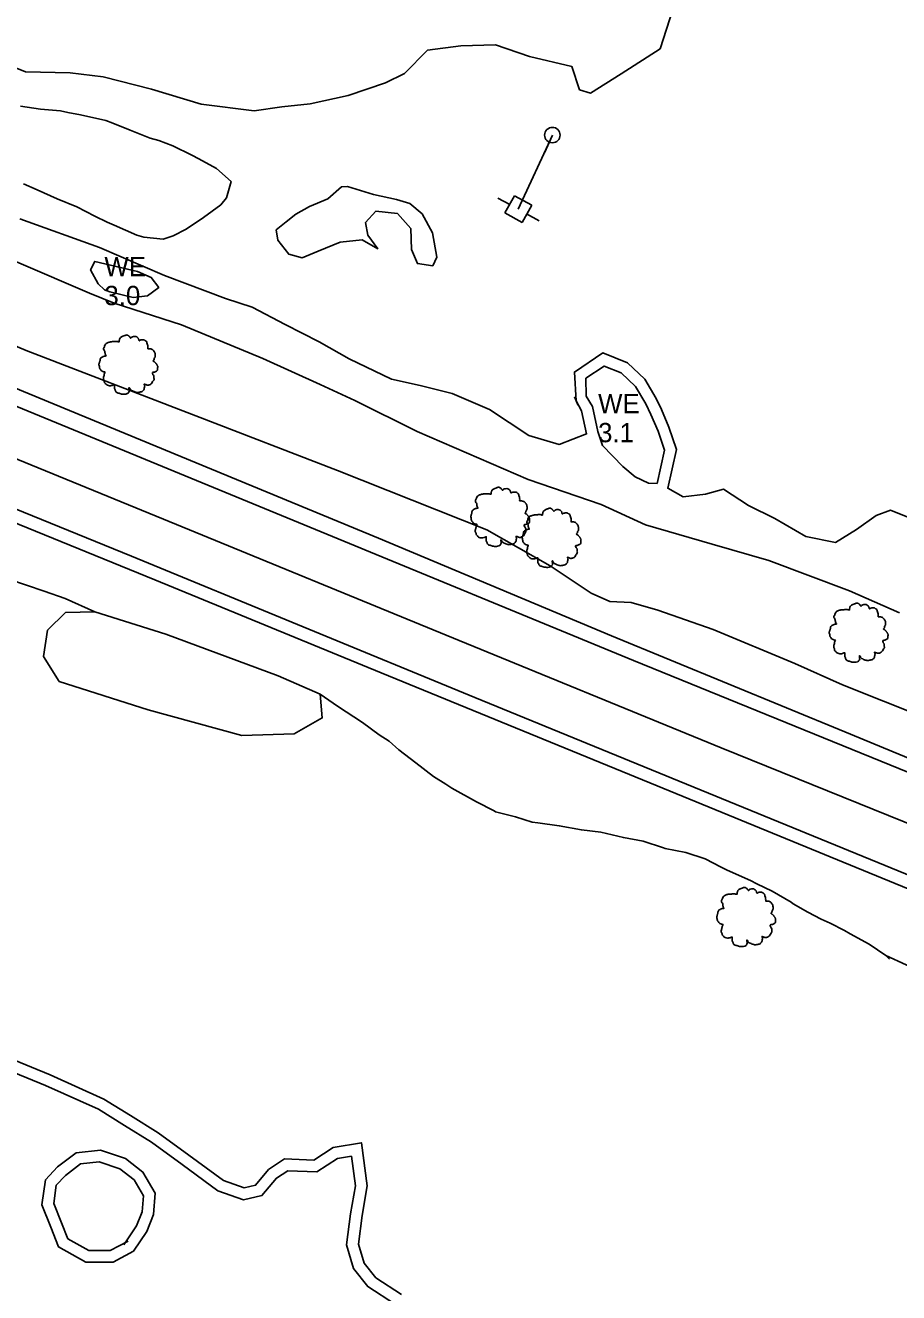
# Model space of a CAD drawing. Extents: x 2160437 to 2172832, y 205694 to 212444.
# Drawn here: x 2165786.1 to 2166012.2, y 209227.2 to 209555.1 of the extents above; entities that cross this region are included whole.
import ezdxf

# ---------------------------------------------------------------- set-up
doc = ezdxf.new("R2010")
doc.units = 0
for name, color, linetype in [('RD_EX_H2O', 7, 'Continuous'), ('RD_EX_H2O_Pond', 7, 'Continuous'), ('RD_EX_H2O_txCode', 7, 'Continuous'), ('RD_EX_LaneStripe', 7, 'Continuous'), ('RD_EX_Road', 7, 'Continuous'), ('RD_EX_UT', 7, 'Continuous'), ('RD_EX_UT_Guy', 7, 'Continuous'), ('RD_EX_VEG', 7, 'Continuous'), ('RD_EX_VEG_ShrubLine', 7, 'Continuous'), ('RD_EX_VEG_TreeLine', 7, 'Continuous')]:
    doc.layers.add(name, color=color, linetype=linetype)

# ---------------------------------------------------------------- blocks, each defined once
blk = doc.blocks.new('T2')
at = {"layer": 'RD_EX_VEG'}
for points in [[(0.05, 7.21), (-0.25, 7.24), (-0.57, 7.14), (-0.82, 7.04), (-1.05, 6.96), (-1.27, 6.86), (-1.57, 6.69), (-1.8, 6.49), (-1.92, 6.24), (-1.97, 6.01), (-2.02, 5.74), (-2.02, 5.56), (-2.15, 5.54), (-2.3, 5.56), (-2.55, 5.64), (-2.8, 5.64), (-3.05, 5.64), (-3.4, 5.61), (-3.75, 5.61), (-4.02, 5.56), (-4.35, 5.51), (-4.72, 5.39), (-5.07, 5.26), (-5.37, 5.01), (-5.62, 4.54), (-5.75, 4.19), (-5.9, 3.94), (-5.75, 3.49), (-5.57, 3.14), (-5.55, 2.94), (-5.47, 2.52), (-5.37, 2.29), (-5.25, 2.09), (-5.32, 2.07), (-5.7, 2.02), (-6, 1.92), (-6.42, 1.69), (-6.64, 1.47), (-6.74, 1.14), (-6.77, 0.79), (-6.87, 0.59), (-6.94, 0.32), (-6.97, 0.24), (-7.02, -0.08), (-6.92, -0.53), (-6.89, -0.88), (-6.77, -1.11), (-6.62, -1.28), (-6.44, -1.53), (-6.05, -1.76), (-5.72, -1.86), (-5.52, -1.88), (-5.7, -2.38), (-5.75, -2.73), (-5.87, -3.13), (-5.87, -3.21), (-5.92, -3.68), (-5.77, -4.01), (-5.7, -4.38), (-5.52, -4.61), (-5.25, -4.91), (-4.92, -5.13), (-4.42, -5.26), (-4.02, -5.23), (-3.45, -5.06), (-3.2, -4.98), (-3.22, -5.16), (-3.2, -5.53), (-3.2, -5.96), (-3.05, -6.28), (-2.95, -6.56), (-2.8, -6.81), (-2.47, -7.03), (-2.07, -7.11), (-1.65, -7.26), (-1.2, -7.33), (-0.7, -7.36), (-0.1, -7.21), (0.18, -7.08), (0.28, -6.91), (0.48, -6.53), (0.43, -6.31), (0.45, -5.71), (0.55, -5.88), (0.73, -6.23), (1.23, -6.53), (1.63, -6.71), (2.1, -6.86), (2.4, -6.93), (2.88, -6.86), (3.25, -6.78), (3.63, -6.66), (3.93, -6.38), (4.1, -6.11), (4.15, -5.83), (4.23, -5.46), (4.28, -5.28)], [(4.28, -5.28), (4.2, -5.11), (4.15, -4.86), (4.23, -4.88), (4.4, -4.93), (4.68, -5.06), (4.9, -5.13), (5.23, -5.11), (5.5, -5.01), (5.95, -4.73), (6.22, -4.26), (6.5, -3.86), (6.57, -3.53), (6.52, -3.31), (6.5, -2.81), (6.3, -2.56), (6.25, -2.43), (6.15, -2.03), (6.22, -1.98), (6.5, -1.93), (6.87, -1.81), (7.15, -1.68), (7.37, -1.51), (7.45, -1.28), (7.42, -0.88), (7.47, -0.48), (7.4, -0.33), (7.3, -0.18), (7.22, 0.02), (7.07, 0.17), (6.97, 0.32), (6.87, 0.42), (6.75, 0.57), (6.57, 0.69), (6.42, 0.74), (6.37, 0.89), (6.52, 1.09), (6.57, 1.19), (6.6, 1.42), (6.82, 1.77), (6.87, 2.17), (6.82, 2.59), (6.77, 2.87), (6.62, 3.14), (6.42, 3.39), (6.3, 3.56), (6.12, 3.69), (5.8, 3.81), (5.55, 3.86), (5.2, 3.86), (5, 3.91), (5.03, 3.96), (5.03, 4.11), (5.03, 4.39), (4.95, 4.84), (4.8, 5.34), (4.8, 5.36), (4.7, 5.61), (4.48, 5.81), (4.3, 5.91), (4.1, 6.04), (3.85, 6.06), (3.55, 6.06), (3.28, 6.01), (3.08, 5.91), (2.9, 5.79), (2.83, 5.94), (2.73, 6.24), (2.68, 6.39), (2.53, 6.56), (2.3, 6.76), (1.85, 6.89), (1.23, 6.81), (0.93, 6.61), (0.78, 6.44), (0.73, 6.56), (0.53, 6.76), (0.43, 6.94), (0.25, 7.06), (0.1, 7.16), (0, 7.21)]]:
    blk.add_spline(points, degree=3, dxfattribs=at)
blk = doc.blocks.new('PP')
at = {"layer": 'RD_EX_UT'}
for p, q in [((2.49, 2.51), (-2.51, 2.51)), ((-2.51, 2.51), (-2.51, -2.49)), ((2.49, -2.49), (2.49, 2.51)), ((-5.94, -0.05), (-2.47, -0.05)), ((-2.51, -2.49), (2.49, -2.49)), ((2.42, -0.05), (6.06, -0.05))]:
    blk.add_line(p, q, dxfattribs=at)

msp = doc.modelspace()

# ---------------------------------------------------------------- linework, layer by layer
at = {"layer": 'RD_EX_H2O'}
msp.add_lwpolyline([(2165881.95, 209224.17), (2165874.74, 209228.78), (2165871.05, 209233.47), (2165869.25, 209239.54), (2165870.28, 209247.57), (2165871.53, 209254.88), (2165870.51, 209262.51), (2165866.92, 209261.88), (2165861.57, 209258.44), (2165854.03, 209258.75), (2165851.09, 209256.83), (2165847.35, 209252.31), (2165842.54, 209251.18), (2165835.96, 209253.56), (2165826.66, 209260.33), (2165818.77, 209266.11), (2165811.76, 209270.45), (2165804.99, 209274.64), (2165791.33, 209280.8), (2165779.76, 209285.54)], dxfattribs=at)
msp.add_lwpolyline([(2165814.1, 209237.89), (2165808.81, 209235.1), (2165801.77, 209235.09), (2165794.66, 209239.03), (2165792.66, 209244.14), (2165790.39, 209249.88), (2165791.27, 209256.35), (2165794.42, 209259.76), (2165799.22, 209263.4), (2165805.56, 209264.08), (2165812, 209261.9), (2165816.53, 209258.39), (2165819.71, 209252.97), (2165819.29, 209247.43), (2165817.58, 209243.06)], close=True, dxfattribs=at)
at = {"layer": 'RD_EX_H2O_Pond'}
for points in [[(2165804.95, 209488.2), (2165802.98, 209491.85), (2165804.05, 209494.05), (2165815.16, 209491.44), (2165818.68, 209489.87), (2165820.64, 209487.32), (2165817.71, 209485.12), (2165813.99, 209484.73), (2165808, 209486.17), (2165806.56, 209486.72)], [(2165934.32, 209450.03), (2165932.91, 209456.47), (2165931.27, 209459.2), (2165931.22, 209463.81), (2165935.95, 209466.98), (2165940.3, 209465.23), (2165944.07, 209461.64), (2165946.71, 209457.16), (2165948, 209454.44), (2165949.89, 209450.11), (2165951.53, 209445.2), (2165949.61, 209436.6), (2165947.42, 209436.67), (2165943.96, 209438.3), (2165940.77, 209440.94), (2165935.51, 209446.37)]]:
    msp.add_lwpolyline(points, close=True, dxfattribs=at)
at = {"layer": 'RD_EX_LaneStripe'}
msp.add_lwpolyline([(2165351.71, 209619.17), (2165398.66, 209599.89), (2165469.92, 209570.6), (2165540.18, 209541.69), (2165609.74, 209513.4), (2165682.5, 209484.08), (2165755.38, 209454.5), (2165825.21, 209425.99), (2165895.04, 209397.29), (2165966.21, 209368.17), (2166025.36, 209344.25)], dxfattribs=at)
at = {"layer": 'RD_EX_Road'}
for points in [[(2165357.09, 209634.04), (2165400.48, 209616.17), (2165463.79, 209590.16), (2165519.82, 209567.3), (2165594.5, 209536.83), (2165634.04, 209521.03), (2165703.73, 209492.82), (2165783.1, 209461.45), (2165877.48, 209422.45), (2165937.8, 209397.18), (2165998.2, 209372.29), (2166026.17, 209360.72)], [(2166024.71, 209357.76), (2165943.48, 209390.77), (2165859.72, 209425.24), (2165772.07, 209461.29), (2165678.08, 209499.62), (2165598.61, 209531.58), (2165479.36, 209579.95), (2165355.66, 209630.84)], [(2165347.69, 209607.9), (2165406.01, 209584.16), (2165513.05, 209539.94), (2165598.18, 209505.37), (2165706.73, 209461.26), (2165813.54, 209417.73), (2165902.46, 209381.16), (2166015.83, 209334.81)], [(2166014.65, 209331.72), (2165949.69, 209358.32), (2165878.21, 209387.6), (2165819.58, 209411.66), (2165762.4, 209434.9), (2165704.62, 209458.26), (2165647.21, 209481.6), (2165576.85, 209510.24), (2165517.3, 209534.48), (2165418.35, 209575.15), (2165346.3, 209604.56)]]:
    msp.add_lwpolyline(points, dxfattribs=at)
at = {"layer": 'RD_EX_UT'}
msp.add_line((2165922.52, 209526.73), (2165920.48, 209522.17), dxfattribs=at)
msp.add_circle((2165922.52, 209526.73), 2, dxfattribs=at)
at = {"layer": 'RD_EX_UT_Guy'}
msp.add_lwpolyline([(2165922.52, 209526.73), (2165913.71, 209507.57)], dxfattribs=at)
at = {"layer": 'RD_EX_VEG_ShrubLine'}
for points in [[(2165774.75, 209547.68), (2165786.14, 209543.07), (2165797.68, 209542.85), (2165806.2, 209541.79), (2165818.79, 209538.65), (2165831.57, 209534.69), (2165845.29, 209533.05), (2165852.53, 209534.01), (2165859.81, 209534.86), (2165869.64, 209536.94), (2165879.3, 209540.28), (2165884.28, 209542.7), (2165890.22, 209548.69), (2165898.79, 209549.79), (2165907.81, 209550.05), (2165916.64, 209547.03), (2165916.64, 209547.03), (2165927.58, 209544.44), (2165929.56, 209538.47), (2165932.42, 209537.56), (2165940.37, 209542.57), (2165950.44, 209549.08), (2165953.67, 209559.19)], [(2165785.6, 209514.15), (2165789.16, 209512.56), (2165794.32, 209510.27), (2165794.32, 209510.27), (2165799.4, 209508.19), (2165804.12, 209505.73), (2165807.27, 209504.24), (2165809.09, 209503.43), (2165814.93, 209500.83), (2165816.78, 209500.28), (2165821.75, 209499.8), (2165824.38, 209500.63), (2165827.72, 209502.42), (2165832.23, 209505.41), (2165832.23, 209505.41), (2165836.69, 209508.7), (2165838.13, 209510.51), (2165839.36, 209514.69), (2165839.36, 209514.69), (2165835.6, 209518.09), (2165830.99, 209520.59), (2165829.23, 209521.55), (2165824.29, 209523.93), (2165820.66, 209525.36), (2165818.44, 209525.9), (2165813.21, 209528.04), (2165808.75, 209529.84), (2165806.97, 209530.54), (2165800.33, 209531.95), (2165797.06, 209532.58), (2165795.18, 209533.05), (2165790, 209533.45), (2165784.8, 209534.22)], [(2166015.36, 209427.53), (2166010.06, 209429.71), (2166006.33, 209428.28), (2166001.29, 209424.7), (2165995.79, 209421.33), (2165988.15, 209422.82), (2165980.11, 209427.53), (2165973.3, 209430.92), (2165966.83, 209435.07), (2165962.2, 209433.85), (2165956.4, 209433.16), (2165952.4, 209435.33), (2165954.64, 209445.36), (2165952.69, 209451.18), (2165950.73, 209455.69), (2165949.36, 209458.56), (2165946.44, 209463.53), (2165941.95, 209467.8), (2165935.6, 209470.36), (2165928.21, 209465.4), (2165928.71, 209457.93), (2165930.09, 209455.35), (2165931.39, 209449.39), (2165924.24, 209446.71), (2165916.45, 209448.99), (2165906.25, 209455.7), (2165896.57, 209459.87), (2165888.28, 209461.97), (2165880.86, 209463.58), (2165869.88, 209468.83), (2165862.14, 209473.27), (2165853.33, 209477.68), (2165844.82, 209482.24), (2165837.93, 209484.44), (2165822.14, 209490.41), (2165805.27, 209497.64), (2165784.63, 209505.04)], [(2165766.6, 209501.26), (2165802.67, 209485.82), (2165809.11, 209483.23), (2165826.52, 209477.63), (2165847.54, 209468.92), (2165862.45, 209462.2), (2165871.39, 209458.09), (2165887.56, 209450), (2165916.24, 209437.57), (2165935.15, 209431.16), (2165946.64, 209425.92), (2165963.87, 209420.85), (2165978.54, 209416.65), (2165999.45, 209408.8), (2166012.38, 209403.15)], [(2166018.87, 209376.05), (2165997.62, 209384.45), (2165985.32, 209390.01), (2165964.14, 209398.78), (2165949.85, 209403.82), (2165942.92, 209405.81), (2165937.42, 209406.03), (2165932.59, 209408.22), (2165921.99, 209415.25), (2165905.56, 209424.59), (2165866.86, 209439.93), (2165830.21, 209454.05), (2165786.28, 209471.03), (2165759.49, 209482.3)], [(2165929.15, 209456.91), (2165928.27, 209458.96)], [(2165781.86, 209411.81), (2165790.96, 209408.68), (2165796.38, 209406.86), (2165804.06, 209403.4)], [(2165862.39, 209382.02), (2165866.93, 209378.95), (2165873.37, 209374.73), (2165877.67, 209371.54), (2165880.24, 209369.86), (2165882.77, 209367.69), (2165887.18, 209364.32), (2165891.78, 209360.77), (2165894.9, 209358.8), (2165896.49, 209357.77), (2165902.88, 209354.16), (2165907.45, 209351.86), (2165907.81, 209351.65), (2165912.96, 209350.36), (2165917.28, 209348.94), (2165918.72, 209348.8), (2165924.31, 209348), (2165930.03, 209346.95), (2165930.03, 209346.95), (2165935.07, 209346.35), (2165940.9, 209344.94), (2165940.9, 209344.94), (2165945.99, 209344.04), (2165951.31, 209342.31), (2165951.69, 209342.14), (2165957.08, 209341.06), (2165962.07, 209339.43), (2165966.26, 209337.3), (2165967.74, 209336.55), (2165973.8, 209333.81), (2165975.47, 209332.98), (2165979.46, 209331.12), (2165984.31, 209328.23), (2165984.85, 209327.81), (2165988.68, 209325.61), (2165992.07, 209323.83), (2165994.42, 209322.78), (2165998.12, 209320.87), (2165999.62, 209320.06), (2166004.52, 209317.39), (2166008.81, 209314.48), (2166009.77, 209313.46)], [(2166008.81, 209314.48), (2166014.14, 209312.02), (2166022.69, 209307.93), (2166033.32, 209302.72), (2166038.82, 209300.66), (2166045.46, 209298.33), (2166050.13, 209296.29), (2166056.06, 209294.4), (2166056.06, 209294.4), (2166063.1, 209292.01), (2166070.03, 209289.67), (2166076.32, 209288.16), (2166081.43, 209287.36), (2166083.55, 209288.2), (2166084.04, 209288.22)], [(2165883.48, 209226.75), (2165876.78, 209231.04), (2165873.76, 209234.87), (2165872.31, 209239.78), (2165873.25, 209247.13), (2165874.56, 209254.82), (2165873.07, 209266), (2165865.8, 209264.73), (2165860.75, 209261.48), (2165853.19, 209261.79), (2165849.07, 209259.09), (2165845.68, 209255), (2165842.72, 209254.31), (2165837.38, 209256.24), (2165828.43, 209262.75), (2165820.45, 209268.59), (2165813.34, 209273), (2165806.4, 209277.3), (2165792.51, 209283.56), (2165781.35, 209288.13)]]:
    msp.add_lwpolyline(points, dxfattribs=at)
msp.add_lwpolyline([(2165856.15, 209506.26), (2165853.58, 209504.26), (2165850.98, 209502.2), (2165851.45, 209499.58), (2165854.28, 209495.91), (2165857.74, 209495.01), (2165861.86, 209496.72), (2165867.61, 209499.03), (2165873.29, 209499.64), (2165877.3, 209497.31), (2165874.78, 209500.84), (2165874.13, 209504.08), (2165876.85, 209507.05), (2165882.44, 209506.43), (2165885.87, 209502.59), (2165886.08, 209497.14), (2165887.58, 209493.47), (2165891.55, 209492.89), (2165892.58, 209495.11), (2165891.51, 209501.4), (2165888.85, 209506.35), (2165885.61, 209509.06), (2165882.14, 209510.06), (2165876.23, 209511.37), (2165869.45, 209513.39), (2165867.93, 209513.33), (2165864.39, 209510.27), (2165859.64, 209508.29)], close=True, dxfattribs=at)
at = {"layer": 'RD_EX_VEG_TreeLine'}
msp.add_lwpolyline([(2165794.81, 209385.34), (2165790.78, 209391.81), (2165791.83, 209398.66), (2165796.53, 209403.21), (2165804.06, 209403.4), (2165822.5, 209397.56), (2165851.57, 209386.82), (2165862.39, 209382.02), (2165862.94, 209375.91), (2165855.64, 209371.84), (2165842.17, 209371.38), (2165817.89, 209377.99)], close=True, dxfattribs=at)
msp.add_lwpolyline([(2165812.69, 209240.54), (2165808.07, 209238.1), (2165802.54, 209238.09), (2165797.06, 209241.13), (2165795.45, 209245.24), (2165793.47, 209250.25), (2165794.11, 209255.01), (2165796.45, 209257.53), (2165800.37, 209260.5), (2165805.23, 209261.02), (2165810.56, 209259.22), (2165814.23, 209256.37), (2165816.65, 209252.26), (2165816.34, 209248.11), (2165814.9, 209244.46), (2165811.61, 209239.56)], dxfattribs=at)

# ---------------------------------------------------------------- block references
at = {"layer": 'RD_EX_UT', "xscale": 1.0199999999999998, "yscale": 1.0199999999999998, "rotation": -28.792571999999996}
msp.add_blockref('PP', (2165913.71, 209507.57), dxfattribs=at)
at = {"layer": 'RD_EX_VEG', "xscale": 1.0499999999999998, "yscale": 1.0499999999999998}
for p in [(2165812.52, 209467.4), (2165908.78, 209428.01), (2165922.09, 209422.59), (2166001.58, 209398.03), (2165972.46, 209324.46)]:
    msp.add_blockref('T2', p, dxfattribs=at)

# ---------------------------------------------------------------- texts
at = {"layer": 'RD_EX_H2O_txCode'}
for s, p in [('WE', (2165806.55, 209490.22)), ('3.0', (2165806.55, 209482.72)), ('WE', (2165934.36, 209454.75)), ('3.1', (2165934.36, 209447.25))]:
    msp.add_text(s, height=5, dxfattribs=at).set_placement(p)

doc.saveas('drawing.dxf')
